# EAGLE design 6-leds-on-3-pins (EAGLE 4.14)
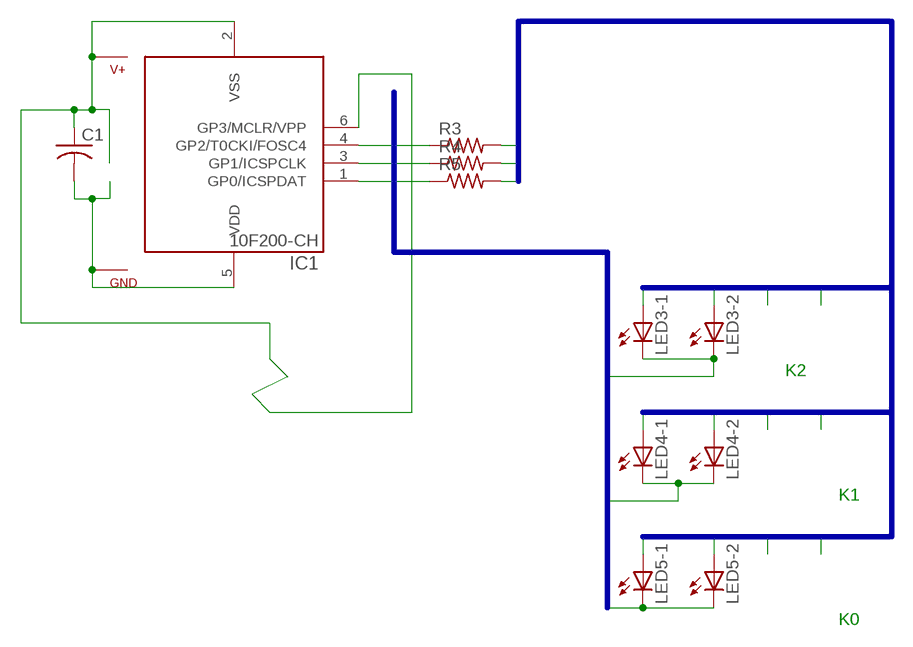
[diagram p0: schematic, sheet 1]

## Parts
C1  C-USC1206  [C1206]
GND  WIRE  [GENERIC1]
IC1  10F200-CH  [SOT23-6L]
LED3-1  LEDSMT1206  [1206]
LED3-2  LEDSMT1206  [1206]
LED4-1  LEDSMT1206  [1206]
LED4-2  LEDSMT1206  [1206]
LED5-1  LEDSMT1206  [1206]
LED5-2  LEDSMT1206  [1206]
R3  R-US_R1206  [R1206]
R4  R-US_R1206  [R1206]
R5  R-US_R1206  [R1206]
V+  WIRE  [GENERIC1]

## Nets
A0: LED3-1.A LED4-1.A R5.2
A1: LED3-2.A LED5-1.A R4.2
A2: LED4-2.A LED5-2.A R3.2
GND: C1.2 GND.P$2 IC1.5(VDD)
K0: IC1.4(GP2/T0CKI/FOSC4) LED5-1.C LED5-2.C R5.1
K1: IC1.3(GP1/ICSPCLK) LED4-1.C LED4-2.C R4.1
K2: IC1.1(GP0/ICSPDAT) LED3-1.C LED3-2.C R3.1
V+: C1.1 IC1.2(VSS) IC1.6(GP3/MCLR/VPP) V+.P$2

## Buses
K[0..4]
A[0..4]

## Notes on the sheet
- K2
- K1
- K0

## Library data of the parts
C1 = rcl:C-US: CAPACITOR, American symbol
GND V+ = mylib:WIRE: Pad for a wire offboard
IC1 = pic-olin:10F20*-?
LED3-1 LED3-2 LED4-1 LED4-2 LED5-1 LED5-2 = led:LED: LED
R3-R5 = rcl:R-US_: RESISTOR, American symbol

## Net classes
0 default: width 0.3 mm
1 power: width 0.3 mm

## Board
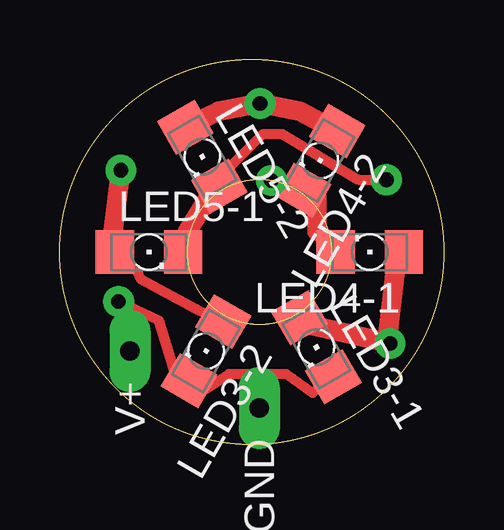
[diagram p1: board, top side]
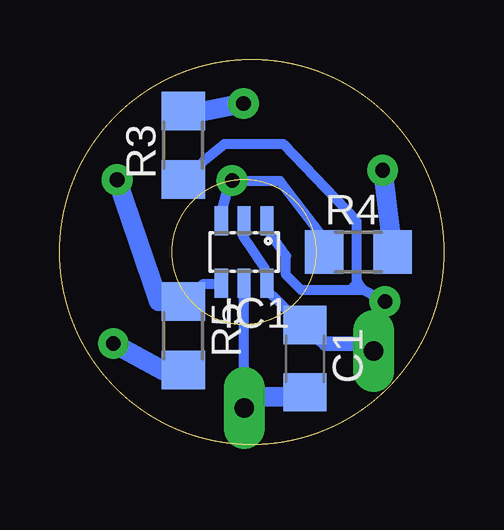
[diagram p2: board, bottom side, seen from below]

Size 16 x 16 mm. Coordinates in mm from the lower left corner, seen from the top.
Outline: circle at 8,8 radius 8
Outline: circle at 8.32,8 radius 3
Copper layers (1*16): Top 0.035mm / dielectric 1.5mm / Bottom 0.035mm
Design rules "default": minimum track width 10mil, minimum drill 24mil, track to track 0.3mm, track to pad 0.4mm, pad to pad 0.4mm, via to via 0.4mm, smd to smd 8mil, copper to edge 40mil, drill to drill 8mil, minimum pad ring 10mil, minimum via ring 8mil, stop-mask expansion 4mil, vias tented up to drill 0mil, thermal gap 10mil

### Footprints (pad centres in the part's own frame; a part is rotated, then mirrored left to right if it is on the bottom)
C1206 = smd 1.6 x 1.8: 1 -1.4,0; 2 1.4,0
GENERIC1 = drill 0.813 long: P$2 0,0
SOT23-6L = smd 0.55 x 1.2: 1 -0.95,-1.3; 2 0,-1.3; 3 0.95,-1.3; 4 0.95,1.3; 5 0,1.3; 6 -0.95,1.3
1206 = smd 1.6 x 1.803: A -1.422,0; C 1.422,0
R1206 = smd 1.6 x 1.803: 1 -1.422,0; 2 1.422,0

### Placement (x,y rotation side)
C1  5.78,3.56 270 bottom
GND  8.32,1.49 270 top
IC1  8.32,8 180 bottom
LED3-1  10.7,4.03 300 top
LED3-2  6.09,3.87 240 top
LED4-1  12.92,8 180 top
LED4-2  10.86,11.81 240 top
LED5-1  3.71,8 0 top
LED5-2  5.94,11.97 300 top
R3  10.86,12.45 90 bottom
R4  3.55,8 0 bottom
R5  10.86,4.51 270 bottom
V+  2.92,3.87 270 top

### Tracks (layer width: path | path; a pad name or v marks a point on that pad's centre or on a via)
A0  (via drill 0.61)
  Top 0.3: 14.09,8.13 LED4-1.A
  Top 0.406: 10.47,4.96 LED3-1.A 13.64,4.19
  Top 0.813: 10.47,4.96 v13.77,4.19 | 13.64,4.19 14.09,8.13
  Bottom 0.406: 11.72,3.08 R5.2
  Bottom 0.813: v13.77,4.19 11.72,3.08
A1  (via drill 0.61)
  Top 0.3: 2.22,8.88 LED5-1.A 3.22,7.18
  Top 0.406: 3.22,7.18 3.35,6.89 5.7,5.62 LED3-2.A
  Top 0.813: 2.22,8.88 v2.54,11.4
  Bottom 0.406: 2.22,8.88 R4.2
  Bottom 0.813: v2.54,11.4 2.22,8.88
A2  (via drill 0.61)
  Top 0.813: LED5-2.A 6.62,13.88 v8.34,14.19 10.02,13.88 LED4-2.A
  Bottom 0.3: 10.02,13.88 R3.2
  Bottom 0.813: v8.34,14.19 10.02,13.88
GND
  Bottom 0.3: 8.32,6.18 IC1.5 | C1.2 6.62,1.98
  Bottom 0.406: 8.32,6.18 8.32,2.48 GND.P$2
  Bottom 0.813: 6.62,1.98 7.82,1.98 GND.P$2
K0  (via drill 0.61)
  Top 0.3: LED5-1.C 5.32,8.88
  Top 0.406: 13.61,11.04 v13.61,11.01 12.45,11.02 9.27,12.92 8.48,12.92 6.77,11.21 LED5-2.C
  Top 0.813: 5.32,8.88 6.27,10.43 LED5-2.C
  Bottom 0.3: 9.52,6.68 IC1.4 | 10.93,5.88 R5.1
  Bottom 0.406: 9.52,6.68 10.02,6.68 R5.1
  Bottom 0.813: 10.93,5.88 11.88,5.94 v13.61,11.01
K1  (via drill 0.61)
  Top 0.3: 10.72,8.88 LED4-1.C | 10.72,10.28 LED4-2.C 10.02,10.98
  Top 0.406: v8.82,10.98 10.02,10.98
  Top 0.813: 10.72,10.28 10.72,8.88
  Bottom 0.3: 9.22,9.56 IC1.3 | v8.82,10.98 8.82,10.58 8.92,10.95
  Bottom 0.406: 9.22,9.56 9.22,9.86 8.92,10.95 6.82,10.95 5.22,8.88 R4.1
K2  (via drill 0.61)
  Top 0.3: 5.38,2.08 5.38,2.16 5.21,2.17 5.05,2.15
  Top 0.406: 5.05,2.15 4.13,5.14 v2.44,5.93 | 5.38,2.08 LED3-2.C 6.09,2.29 7.05,2.92 9.43,2.92 10.53,2.13 LED3-1.C
  Bottom 0.3: 3.62,6.78 3.61,6.78 3.92,6.48 | 10.02,11.78 R3.1
  Bottom 0.406: 3.62,6.78 3.62,9.28 6.68,12.49 9.14,12.49 10.02,11.78 | v2.44,5.93 3.37,6.43 | 3.37,6.43 3.61,6.78 | IC1.1 7.37,8.96 6.57,7.84 6.57,7.05 5.94,6.41 3.4,6.41 3.38,6.43 3.37,6.43
V+
  Bottom 0.3: 7.12,6.18 IC1.6 | C1.1 6.62,5.68
  Bottom 0.406: 6.62,5.68 7.12,6.18 | IC1.2 8.38,9.09 8.38,8.69 7.44,7.28 IC1.6
  Bottom 0.61: V+.P$2 3.72,4.18 4.92,4.18 C1.1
